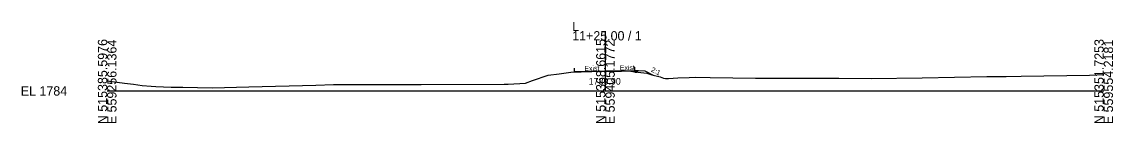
# Model space of a CAD drawing. Extents: x -26 to 1303, y -10 to 9545.
# Drawn here: x -25.7 to 302.8, y 2990.3 to 3020.8 of the extents above; entities that cross this region are included whole.
import ezdxf

# ---------------------------------------------------------------- set-up
doc = ezdxf.new("R2010")
doc.units = 0
for name, color, linetype in [('Exist Cross Section Cell', 7, 'Continuous'), ('Exist XS Center Line Elevation Label', 7, 'Continuous'), ('Exist XS Ground Line', 7, 'Continuous'), ('Prop XS Ditch Slope Text', 7, 'Continuous'), ('Prop XS EOT Tick Mark', 7, 'Continuous'), ('Prop XS Finish Grade', 7, 'Continuous'), ('Prop XS Finish Grade Earthwork', 7, 'Continuous'), ('Prop XS Finish Grade Pavement', 7, 'Continuous'), ('Prop XS Pvmt Edge Slope', 7, 'Continuous'), ('Prop XS SE Text', 7, 'Continuous'), ('Prop XS Subgrade Earthwork', 7, 'Continuous')]:
    doc.layers.add(name, color=color, linetype=linetype)

msp = doc.modelspace()

# ---------------------------------------------------------------- linework, layer by layer
at = {"layer": 'Exist Cross Section Cell'}
for p, q in [((150, 3000), (150, 3017.97)), ((0, 3000), (150, 3000)), ((150, 3000), (300, 3000))]:
    msp.add_line(p, q, dxfattribs=at)
at = {"layer": 'Exist XS Ground Line'}
for p, q in [((0, 3003.04), (5.21, 3002.38)), ((125.93, 3002.31), (128.07, 3003.09)), ((128.07, 3003.09), (132.76, 3004.7)), ((132.76, 3004.7), (136.09, 3005.17)), ((136.09, 3005.17), (139.59, 3005.62)), ((139.59, 3005.62), (149, 3005.89)), ((149, 3005.89), (150, 3005.9)), ((150, 3005.9), (154.87, 3005.97)), ((154.87, 3005.97), (157.04, 3005.99)), ((157.04, 3005.99), (158.81, 3005.78)), ((158.81, 3005.78), (162.49, 3005.29)), ((162.49, 3005.29), (164, 3004.86)), ((164, 3004.86), (166.43, 3004.2)), ((166.43, 3004.2), (167.51, 3003.82)), ((167.51, 3003.82), (168.05, 3003.7)), ((168.05, 3003.7), (168.94, 3003.76)), ((168.94, 3003.76), (171.75, 3003.98)), ((171.75, 3003.98), (175.18, 3004.06)), ((175.18, 3004.06), (177.09, 3004.09)), ((177.09, 3004.09), (181.53, 3004.06)), ((181.53, 3004.06), (195.13, 3003.87)), ((195.13, 3003.87), (208.12, 3003.79)), ((208.12, 3003.79), (220.28, 3003.8)), ((220.28, 3003.8), (229.95, 3003.74)), ((229.95, 3003.74), (245.39, 3003.97)), ((245.39, 3003.97), (264.84, 3004.31)), ((264.84, 3004.31), (270.6, 3004.36)), ((270.6, 3004.36), (275.16, 3004.4)), ((275.16, 3004.4), (295.72, 3004.73)), ((295.72, 3004.73), (300, 3004.9)), ((5.21, 3002.38), (7.89, 3002.07)), ((7.89, 3002.07), (10.57, 3001.58)), ((10.57, 3001.58), (13.25, 3001.41)), ((13.25, 3001.41), (14.67, 3001.33)), ((14.67, 3001.33), (19.25, 3001.17)), ((19.25, 3001.17), (22.81, 3001.09)), ((22.81, 3001.09), (31.58, 3000.95)), ((31.58, 3000.95), (42.69, 3001.21)), ((42.69, 3001.21), (62.81, 3001.76)), ((62.81, 3001.76), (68.15, 3001.89)), ((68.15, 3001.89), (68.89, 3001.91)), ((68.89, 3001.91), (69.59, 3001.92)), ((69.59, 3001.92), (71.84, 3001.93)), ((71.84, 3001.93), (93.94, 3001.93)), ((93.94, 3001.93), (94.53, 3001.93)), ((94.53, 3001.93), (119.48, 3002.04)), ((119.48, 3002.04), (120.68, 3002.04)), ((120.68, 3002.04), (125.93, 3002.31))]:
    msp.add_line(p, q, dxfattribs=at)
at = {"layer": 'Prop XS EOT Tick Mark'}
for p, q in [((140.72, 3005.81), (140.72, 3006.81)), ((158.88, 3006.17), (158.88, 3007.17))]:
    msp.add_line(p, q, dxfattribs=at)
at = {"layer": 'Prop XS Finish Grade'}
msp.add_line((158.88, 3006.17), (159.9, 3006.14), dxfattribs=at)
at = {"layer": 'Prop XS Finish Grade Earthwork'}
for p, q in [((159.9, 3006.14), (161.88, 3006.01)), ((161.88, 3006.01), (164.38, 3004.76))]:
    msp.add_line(p, q, dxfattribs=at)
at = {"layer": 'Prop XS Finish Grade Pavement'}
for p, q in [((150, 3006.03), (158.88, 3006.17)), ((140.72, 3005.81), (150, 3006.03))]:
    msp.add_line(p, q, dxfattribs=at)
at = {"layer": 'Prop XS Pvmt Edge Slope'}
msp.add_line((158.88, 3006.17), (159.41, 3005.64), dxfattribs=at)
at = {"layer": 'Prop XS Subgrade Earthwork'}
for p, q in [((159.41, 3005.64), (159.9, 3006.14)), ((158.88, 3005.63), (158.88, 3005.8)), ((158.88, 3005.63), (159.41, 3005.64))]:
    msp.add_line(p, q, dxfattribs=at)

# ---------------------------------------------------------------- texts
at = {"layer": 'Exist Cross Section Cell'}
for s, p in [('L', (140, 3017.97)), ('11+25.00 / 1', (140, 3015.17)), ('EL 1784', (-26, 2998.6))]:
    msp.add_text(s, height=2.8, dxfattribs=at).set_placement(p)
for s, p in [('N 515385.5976', (0, 2990)), ('E 559256.1364', (2.8, 2990)), ('N 515368.6615', (150, 2990)), ('E 559405.1772', (152.8, 2990)), ('N 515351.7253', (300, 2990)), ('E 559554.2181', (302.8, 2990))]:
    msp.add_text(s, height=2.8, rotation=90, dxfattribs=at).set_placement(p)
at = {"layer": 'Exist XS Center Line Elevation Label'}
msp.add_text('1789.90', height=2, dxfattribs=at).set_placement((144.94, 3001.9))
at = {"layer": 'Prop XS Ditch Slope Text'}
msp.add_text('2:1', height=1.5, rotation=333.4349, dxfattribs=at).set_placement((163.58, 3005.9))
at = {"layer": 'Prop XS SE Text'}
for p in [(143.68, 3006.01), (154.36, 3006.2)]:
    msp.add_text('Exist', height=1.5, rotation=1.3214, dxfattribs=at).set_placement(p)

doc.saveas('drawing.dxf')
